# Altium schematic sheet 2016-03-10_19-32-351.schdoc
size 298 x 172 mm; SheetNumber: 1; SheetTotal: 1
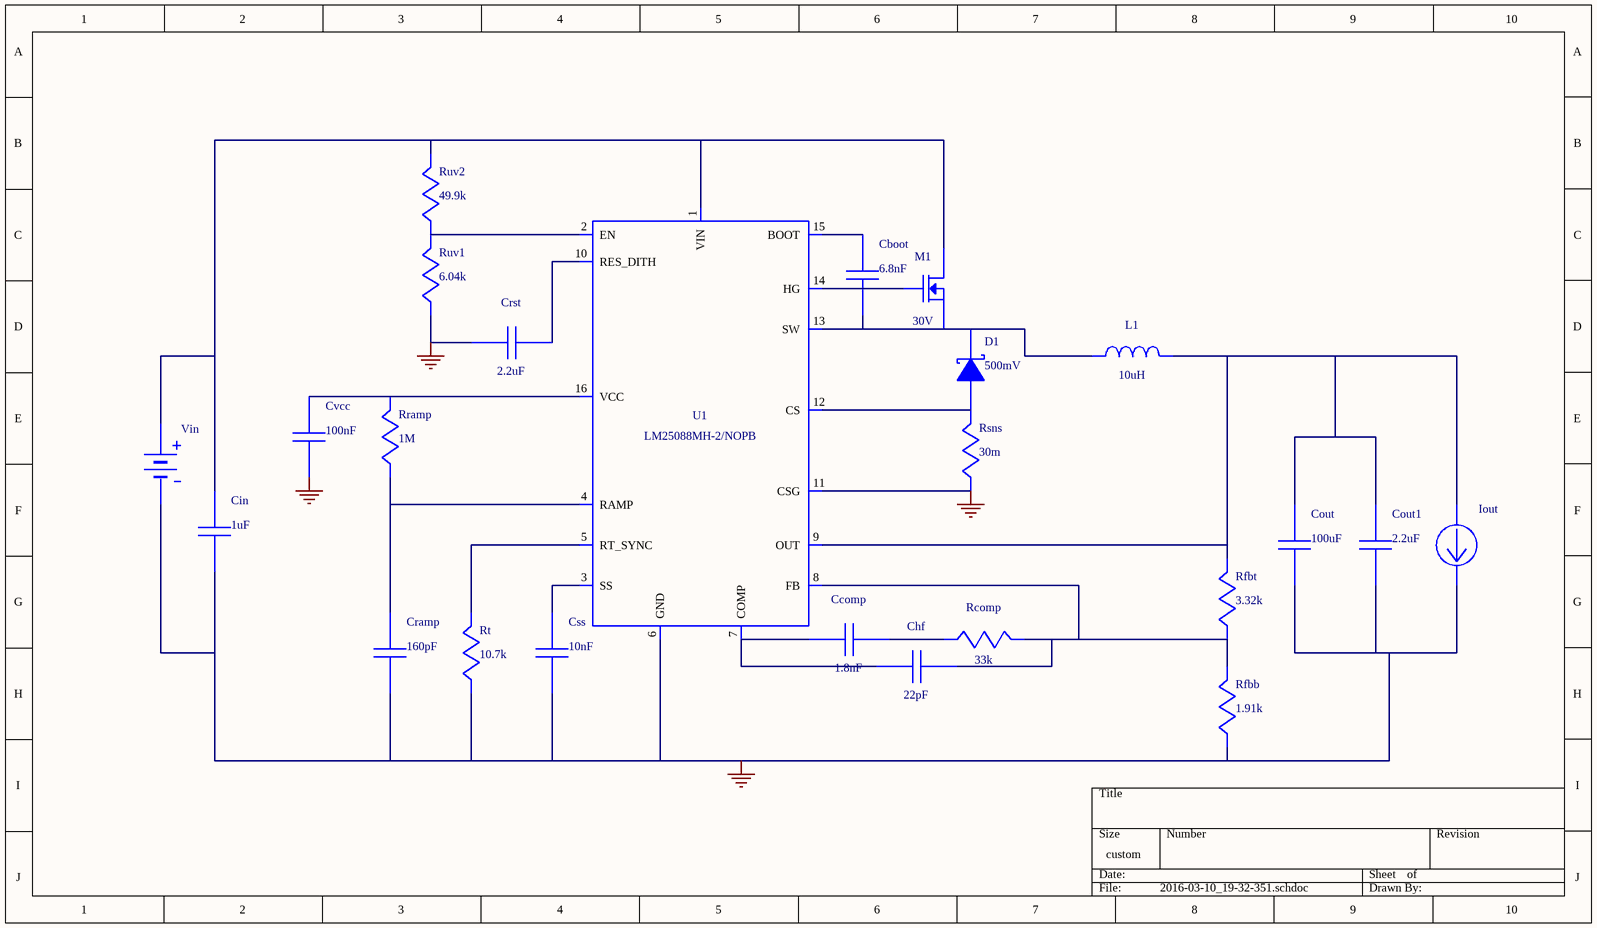
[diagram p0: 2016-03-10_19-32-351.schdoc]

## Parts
Cboot  value 6.8nF  (hidden comment: C0603C682K5RACTU)
Ccomp  value 1.8nF  (hidden comment: GRM188R71H182KA01D)
Chf  value 22pF  (hidden comment: C0603C220K3GACTU)
Cin  value 1uF  (hidden comment: GENERIC_CAPACITOR)
Cout  value 100uF  (hidden comment: GRM31CR60J107ME39L)
Cout1  value 2.2uF  (hidden comment: GRM188R60J225KE19D)
Cramp  value 160pF  (hidden comment: CL10C161JB8NNNC)
Crst  value 2.2uF  (hidden comment: C0603C225K9PACTU)
Css  value 10nF  (hidden comment: C0603C103J5RACTU)
Cvcc  value 100nF  (hidden comment: C0603C104K3RACTU)
D1  value 500mV  (hidden comment: B340A-13-F)
Iout  WB_CURRENT_LOAD  (value not drawn)
L1  value 10uH  (hidden comment: SRU1038-100Y)
M1  value 30V  (hidden comment: CSD17308Q3)
Rcomp  value 33k  (hidden comment: RC0603FR-0733KL)
Rfbb  value 1.91k  (hidden comment: CRCW04021K91FKED)
Rfbt  value 3.32k  (hidden comment: CRCW04023K32FKED)
Rramp  value 1M  (hidden comment: CRCW06031M00FKEA)
Rsns  value 30m  (hidden comment: CSR1206FK30L0)
Rt  value 10.7k  (hidden comment: CRCW060310K7FKEA)
Ruv1  value 6.04k  (hidden comment: ERJ-6ENF6041V)
Ruv2  value 49.9k  (hidden comment: ERJ-6ENF4992V)
U1  LM5088MH-2  (value not drawn)
Vin  WB_BATTERY  (value not drawn)

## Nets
0: Cin.2 Cout.2 Cout1.2 Cramp.2 Crst.1 Css.2 Cvcc.2 Iout.2(-) Rfbb.2 Rsns.2 Rt.2 Ruv1.2 U1.6(GND) U1.11(CSG) U1.17(EP) Vin.2(-)
NetCboot_1: Cboot.1 D1.1(K) L1.1 M1.1(Source) M1.2(Source) M1.3(Source) U1.13(SW)
NetCboot_2: Cboot.2 U1.15(BOOT)
NetCcomp_1: Ccomp.1 Rcomp.2
NetCcomp_2: Ccomp.2 Chf.1 U1.7(COMP)
NetChf_2: Chf.2 Rcomp.1 Rfbb.1 Rfbt.2 U1.8(FB)
NetCin_1: Cin.1 M1.5(Drain) M1.6(Drain) M1.7(Drain) M1.8(Drain) M1.9(Drain) Ruv2.1 U1.1(VIN) Vin.1(+)
NetCout_1: Cout.1 Cout1.1 Iout.1(+) L1.2 Rfbt.1 U1.9(OUT)
NetCramp_1: Cramp.1 Rramp.2 U1.4(RAMP)
NetCrst_2: Crst.2 U1.10(RES_DITH)
NetCss_1: Css.1 U1.3(SS)
NetCvcc_1: Cvcc.1 Rramp.1 U1.16(VCC)
NetD1_2: D1.2(A) Rsns.1 U1.12(CS)
NetM1_4: M1.4(Gate) U1.14(HG)
NetRt_1: Rt.1 U1.5(RT_SYNC)
NetRuv1_1: Ruv1.1 Ruv2.2 U1.2(EN)

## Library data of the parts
Cboot = C0603C682K5RACTU: Manufacturer Name: Kemet
Ccomp = GRM188R71H182KA01D: GRM188R71H182KA0; Manufacturer Name: MuRata
Chf = C0603C220K3GACTU: Manufacturer Name: Kemet
Cin = GENERIC_CAPACITOR: C1608X7R1V105K08; Manufacturer Name: TDK
Cout = GRM31CR60J107ME39L: GRM31CR60J107ME3; Manufacturer Name: MuRata
Cout1 = GRM188R60J225KE19D: GRM188R60J225KE1; Manufacturer Name: MuRata
Cramp = CL10C161JB8NNNC: Manufacturer Name: Samsung Electro-Mechanics
Crst = C0603C225K9PACTU: Manufacturer Name: Kemet
Css = C0603C103J5RACTU: Manufacturer Name: Kemet
Cvcc = C0603C104K3RACTU: Manufacturer Name: Kemet
D1 = B340A-13-F: Manufacturer Name: Diodes Inc.
Iout = WB_CURRENT_LOAD: Value: UNLISTED
L1 = SRU1038-100Y: Manufacturer Name: Bourns
M1 = CSD17308Q3: Manufacturer Name: Texas Instruments
Rcomp = RC0603FR-0733KL: Manufacturer Name: Yageo America
Rfbb = CRCW04021K91FKED: Manufacturer Name: Vishay-Dale
Rfbt = CRCW04023K32FKED: Manufacturer Name: Vishay-Dale
Rramp = CRCW06031M00FKEA: Manufacturer Name: Vishay-Dale
Rsns = CSR1206FK30L0: Manufacturer Name: Stackpole Electronics Inc
Rt = CRCW060310K7FKEA: Manufacturer Name: Vishay-Dale
Ruv1 = ERJ-6ENF6041V: Manufacturer Name: Panasonic
Ruv2 = ERJ-6ENF4992V: Manufacturer Name: Panasonic
U1 = LM5088MH-2: LM25088MH-2/NOPB; Manufacturer Name: Texas Instruments; Value: UNLISTED
Vin = WB_BATTERY: Value: UNLISTED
